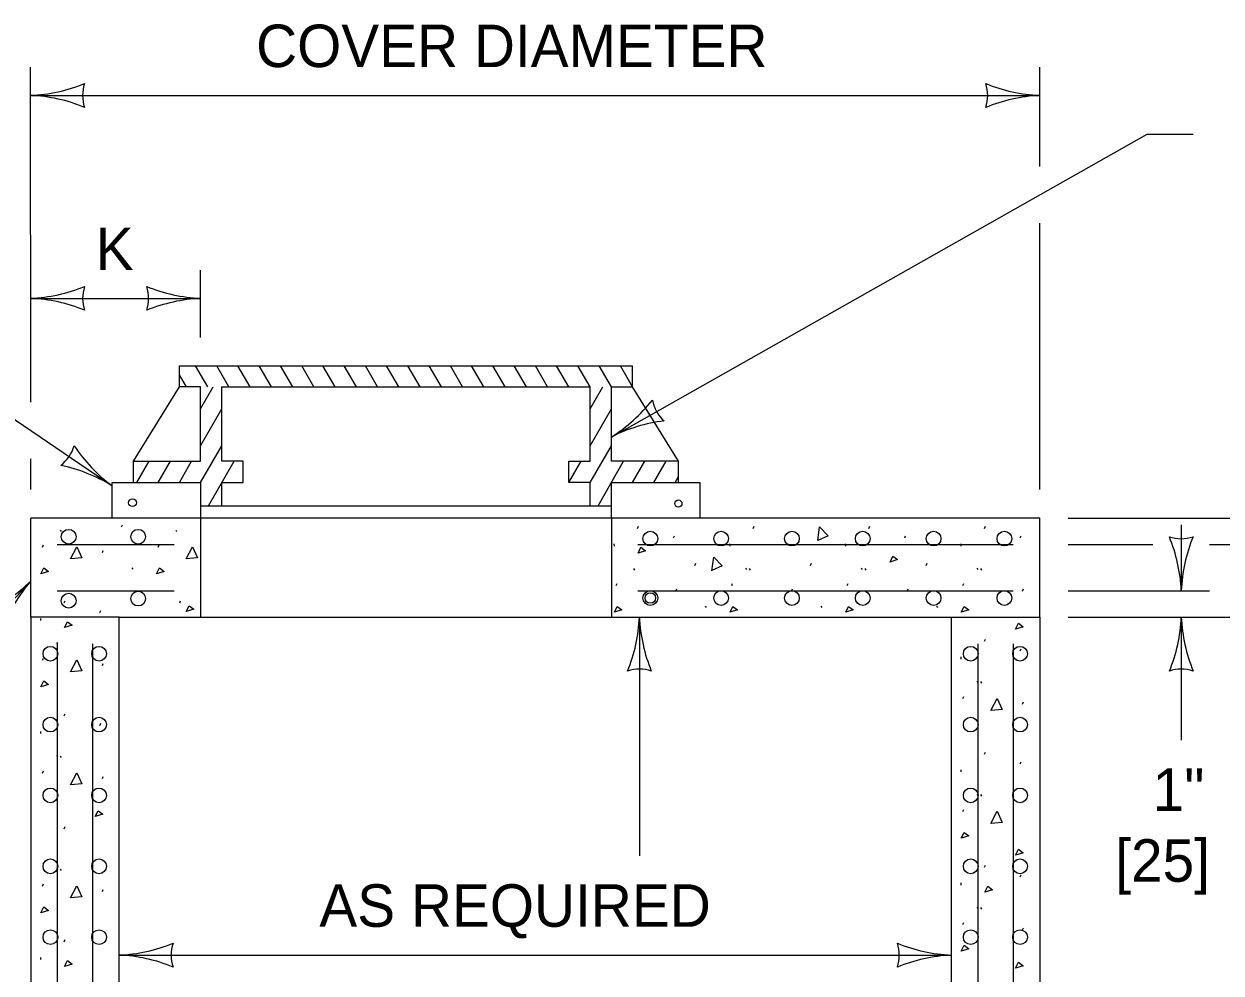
# Model space of a CAD drawing. Extents: x 49991.4 to 50028.3, y 49987.6 to 50011.4.
# Drawn here: x 50007.028 to 50008.719, y 49990.975 to 49992.315 of the extents above; entities that cross this region are included whole.
import ezdxf

# ---------------------------------------------------------------- set-up
doc = ezdxf.new("R2010")
doc.units = 0
for name, color, linetype in [('Level 1', 7, 'Continuous'), ('Level 2', 7, 'Continuous'), ('Level 3', 7, 'Continuous')]:
    doc.layers.add(name, color=color, linetype=linetype)

msp = doc.modelspace()

# ---------------------------------------------------------------- linework, layer by layer
at = {"layer": 'Level 1'}
for p, q in [((50007.2476, 49991.8027), (50007.2476, 49991.8327)), ((50007.2476, 49991.8327), (50007.2776, 49991.8327)), ((50007.2576, 49991.8027), (50007.2476, 49991.82)), ((50007.2876, 49991.8027), (50007.2703, 49991.8327)), ((50007.2776, 49991.8327), (50007.8876, 49991.8327)), ((50007.3176, 49991.8027), (50007.3003, 49991.8327)), ((50007.3476, 49991.8027), (50007.3303, 49991.8327)), ((50007.3776, 49991.8027), (50007.3603, 49991.8327)), ((50007.4076, 49991.8027), (50007.3903, 49991.8327)), ((50007.4376, 49991.8027), (50007.4203, 49991.8327)), ((50007.4676, 49991.8027), (50007.4503, 49991.8327)), ((50007.4976, 49991.8027), (50007.4803, 49991.8327)), ((50007.5276, 49991.8027), (50007.5103, 49991.8327)), ((50007.5576, 49991.8027), (50007.5403, 49991.8327)), ((50007.5876, 49991.8027), (50007.5703, 49991.8327)), ((50007.6176, 49991.8027), (50007.6003, 49991.8327)), ((50007.6476, 49991.8027), (50007.6303, 49991.8327)), ((50007.6776, 49991.8027), (50007.6603, 49991.8327)), ((50007.7076, 49991.8027), (50007.6903, 49991.8327)), ((50007.7376, 49991.8027), (50007.7203, 49991.8327)), ((50007.7676, 49991.8027), (50007.7503, 49991.8327)), ((50007.7976, 49991.8027), (50007.7803, 49991.8327)), ((50007.8276, 49991.8027), (50007.8103, 49991.8327)), ((50007.8576, 49991.8027), (50007.8403, 49991.8327)), ((50007.8876, 49991.8027), (50007.8703, 49991.8327)), ((50007.8876, 49991.8027), (50007.8876, 49991.8327)), ((50007.1826, 49991.6977), (50007.2476, 49991.8027)), ((50007.2776, 49991.8027), (50007.2476, 49991.8027)), ((50007.2776, 49991.6977), (50007.2776, 49991.8027)), ((50007.2776, 49991.7716), (50007.2955, 49991.8027)), ((50007.3076, 49991.6977), (50007.3076, 49991.8027)), ((50007.3076, 49991.8027), (50007.8276, 49991.8027)), ((50007.8276, 49991.6977), (50007.8276, 49991.8027)), ((50007.8276, 49991.7716), (50007.8455, 49991.8027)), ((50007.8576, 49991.6977), (50007.8576, 49991.8027)), ((50007.8576, 49991.8027), (50007.8876, 49991.8027)), ((50007.9526, 49991.6977), (50007.8876, 49991.8027)), ((50007.2776, 49991.7196), (50007.3076, 49991.7716)), ((50007.8276, 49991.7197), (50007.8576, 49991.7716)), ((50007.2776, 49991.6677), (50007.3076, 49991.7196)), ((50007.8276, 49991.6677), (50007.8576, 49991.7196)), ((50007.1826, 49991.6677), (50007.1826, 49991.6977)), ((50007.1826, 49991.6977), (50007.2776, 49991.6977)), ((50007.1876, 49991.6677), (50007.2049, 49991.6977)), ((50007.2176, 49991.6677), (50007.2349, 49991.6977)), ((50007.2476, 49991.6677), (50007.2649, 49991.6977)), ((50007.2888, 49991.6351), (50007.3249, 49991.6977)), ((50007.3376, 49991.6977), (50007.3076, 49991.6977)), ((50007.3376, 49991.6677), (50007.3376, 49991.6977)), ((50007.7976, 49991.6677), (50007.7976, 49991.6977)), ((50007.7976, 49991.6977), (50007.8276, 49991.6977)), ((50007.7976, 49991.6677), (50007.8149, 49991.6977)), ((50007.8388, 49991.6351), (50007.8749, 49991.6977)), ((50007.9526, 49991.6977), (50007.8576, 49991.6977)), ((50007.8876, 49991.6677), (50007.9049, 49991.6977)), ((50007.9176, 49991.6677), (50007.9349, 49991.6977)), ((50007.9526, 49991.6677), (50007.9526, 49991.6977)), ((50007.1526, 49991.6177), (50007.1526, 49991.6677)), ((50007.1526, 49991.6677), (50007.2776, 49991.6677)), ((50007.2776, 49991.6677), (50007.2776, 49991.6177)), ((50007.3076, 49991.6351), (50007.3076, 49991.6677)), ((50007.3076, 49991.6677), (50007.3376, 49991.6677)), ((50007.8276, 49991.6677), (50007.7976, 49991.6677)), ((50007.8276, 49991.6351), (50007.8276, 49991.6677)), ((50007.8576, 49991.6177), (50007.8576, 49991.6677)), ((50007.8576, 49991.6677), (50007.9826, 49991.6677)), ((50007.9476, 49991.6677), (50007.9526, 49991.6763)), ((50007.9826, 49991.6677), (50007.9826, 49991.6177)), ((50007.2776, 49991.6351), (50007.8576, 49991.6351)), ((50007.0376, 49991.4777), (50007.0376, 49991.6177)), ((50008.4626, 49991.6177), (50007.0376, 49991.6177)), ((50007.2776, 49991.6177), (50007.2776, 49991.4777)), ((50007.8576, 49991.6177), (50007.8576, 49991.4777)), ((50008.4626, 49991.4777), (50008.4626, 49991.6177)), ((50007.0791, 49991.6005), (50007.0805, 49991.5985)), ((50007.1657, 49991.6052), (50007.1671, 49991.6082)), ((50007.2424, 49991.6005), (50007.2437, 49991.5985)), ((50007.8947, 49991.6031), (50007.896, 49991.6061)), ((50008.0579, 49991.6031), (50008.0593, 49991.6061)), ((50008.2212, 49991.6031), (50008.2225, 49991.6061)), ((50008.3845, 49991.6031), (50008.3858, 49991.6061)), ((50007.0751, 49991.5801), (50007.2401, 49991.5801)), ((50007.8612, 49991.5811), (50007.8615, 49991.5781)), ((50007.8951, 49991.5801), (50008.4251, 49991.5801)), ((50007.9453, 49991.5895), (50007.9467, 49991.5925)), ((50008.0245, 49991.5811), (50008.0248, 49991.5781)), ((50008.1877, 49991.5811), (50008.1881, 49991.5781)), ((50008.2718, 49991.5895), (50008.2732, 49991.5925)), ((50008.351, 49991.5811), (50008.3513, 49991.5781)), ((50008.4351, 49991.5895), (50008.4364, 49991.5925)), ((50007.0544, 49991.5766), (50007.0557, 49991.5796)), ((50007.1388, 49991.5689), (50007.1401, 49991.5719)), ((50007.2177, 49991.5766), (50007.219, 49991.5796)), ((50007.1804, 49991.5476), (50007.1817, 49991.5456)), ((50007.889, 49991.5462), (50007.8903, 49991.5442)), ((50007.9756, 49991.5508), (50007.9769, 49991.5538)), ((50008.0472, 49991.5469), (50008.0485, 49991.5449)), ((50008.0523, 49991.5462), (50008.0536, 49991.5442)), ((50008.1389, 49991.5508), (50008.1402, 49991.5538)), ((50008.2105, 49991.5469), (50008.2118, 49991.5449)), ((50008.2155, 49991.5462), (50008.2169, 49991.5442)), ((50008.3021, 49991.5508), (50008.3035, 49991.5538)), ((50008.3737, 49991.5469), (50008.3751, 49991.5449)), ((50008.3788, 49991.5462), (50008.3801, 49991.5442)), ((50007.0751, 49991.5151), (50007.2401, 49991.5151)), ((50007.8643, 49991.5223), (50007.8656, 49991.5252)), ((50007.8951, 49991.5151), (50008.4251, 49991.5151)), ((50007.9486, 49991.5146), (50007.95, 49991.5176)), ((50008.0275, 49991.5223), (50008.0289, 49991.5252)), ((50008.1119, 49991.5146), (50008.1132, 49991.5176)), ((50008.1908, 49991.5223), (50008.1921, 49991.5252)), ((50008.2752, 49991.5146), (50008.2765, 49991.5176)), ((50008.3541, 49991.5223), (50008.3554, 49991.5252)), ((50008.4384, 49991.5146), (50008.4398, 49991.5176)), ((50007.0848, 49991.498), (50007.0861, 49991.501)), ((50007.2481, 49991.498), (50007.2494, 49991.501)), ((50007.1355, 49991.4843), (50007.1368, 49991.4873)), ((50007.9903, 49991.4933), (50007.9916, 49991.4913)), ((50008.1535, 49991.4933), (50008.1549, 49991.4913)), ((50008.3168, 49991.4933), (50008.3181, 49991.4913)), ((50007.1626, 49991.4777), (50007.0376, 49991.4777)), ((50007.0376, 49991.4777), (50007.0376, 49989.7777)), ((50007.0513, 49991.476), (50007.0517, 49991.473)), ((50008.3376, 49991.4777), (50008.4626, 49991.4777)), ((50008.4626, 49991.4777), (50008.4626, 49989.7777)), ((50008.3845, 49991.4437), (50008.3858, 49991.4467)), ((50007.0741, 49991.4418), (50007.0754, 49991.4398)), ((50007.0751, 49991.4401), (50007.0751, 49989.8151)), ((50007.1251, 49991.4401), (50007.1251, 49989.8151)), ((50008.3751, 49991.4401), (50008.3751, 49989.8151)), ((50008.4251, 49991.4401), (50008.4251, 49989.8151)), ((50008.4351, 49991.43), (50008.4364, 49991.433)), ((50007.0544, 49991.4171), (50007.0557, 49991.4201)), ((50007.1388, 49991.4095), (50007.1401, 49991.4125)), ((50008.351, 49991.4216), (50008.3513, 49991.4186)), ((50008.3737, 49991.3875), (50008.3751, 49991.3855)), ((50008.3788, 49991.3867), (50008.3801, 49991.3847)), ((50008.3541, 49991.3628), (50008.3554, 49991.3658)), ((50008.4384, 49991.3551), (50008.4398, 49991.3581)), ((50007.0848, 49991.3385), (50007.0861, 49991.3415)), ((50007.1355, 49991.3249), (50007.1368, 49991.3279)), ((50007.0513, 49991.3165), (50007.0517, 49991.3135)), ((50007.0741, 49991.2824), (50007.0754, 49991.2804)), ((50007.0791, 49991.2816), (50007.0805, 49991.2796)), ((50008.3845, 49991.2842), (50008.3858, 49991.2872)), ((50007.0544, 49991.2577), (50007.0557, 49991.2607)), ((50008.351, 49991.2622), (50008.3513, 49991.2592)), ((50008.4351, 49991.2705), (50008.4364, 49991.2735)), ((50007.1388, 49991.25), (50007.1401, 49991.253)), ((50008.3737, 49991.228), (50008.3751, 49991.226)), ((50008.3788, 49991.2273), (50008.3801, 49991.2253)), ((50008.3541, 49991.2033), (50008.3554, 49991.2063)), ((50007.0848, 49991.1791), (50007.0861, 49991.1821)), ((50008.3845, 49991.1247), (50008.3858, 49991.1277)), ((50007.0741, 49991.1229), (50007.0754, 49991.1209)), ((50007.0791, 49991.1221), (50007.0805, 49991.1201)), ((50008.4351, 49991.1111), (50008.4364, 49991.1141)), ((50007.0544, 49991.0982), (50007.0557, 49991.1012)), ((50007.1388, 49991.0906), (50007.1401, 49991.0935)), ((50008.351, 49991.1027), (50008.3513, 49991.0997)), ((50008.3737, 49991.0685), (50008.3751, 49991.0665)), ((50008.3788, 49991.0678), (50008.3801, 49991.0658)), ((50008.3541, 49991.0439), (50008.3554, 49991.0469)), ((50008.4384, 49991.0362), (50008.4398, 49991.0392)), ((50007.0848, 49991.0196), (50007.0861, 49991.0226)), ((50007.0513, 49990.9976), (50007.0517, 49990.9946))]:
    msp.add_line(p, q, dxfattribs=at)
for points in [[(50008.1491, 49991.586), (50008.1517, 49991.6051), (50008.1637, 49991.5927), (50008.1494, 49991.5861)], [(50007.0938, 49991.5599), (50007.1028, 49991.5769), (50007.1098, 49991.5613), (50007.0941, 49991.5599)], [(50007.2571, 49991.5599), (50007.2661, 49991.5769), (50007.2731, 49991.5613), (50007.2574, 49991.5599)], [(50007.8953, 49991.5681), (50007.8993, 49991.5765), (50007.906, 49991.5715), (50007.8953, 49991.5681)], [(50008.2511, 49991.5555), (50008.2551, 49991.5639), (50008.2618, 49991.5589), (50008.2511, 49991.5555)], [(50007.0521, 49991.5389), (50007.0561, 49991.5473), (50007.0627, 49991.5423), (50007.0521, 49991.5389)], [(50007.2153, 49991.5389), (50007.2193, 49991.5473), (50007.226, 49991.5423), (50007.2153, 49991.5389)], [(50007.9995, 49991.5433), (50008.0021, 49991.5623), (50008.014, 49991.55), (50007.9997, 49991.5434)], [(50007.2572, 49991.4856), (50007.2612, 49991.4939), (50007.2679, 49991.4889), (50007.2572, 49991.4856)], [(50007.8619, 49991.4846), (50007.8659, 49991.4929), (50007.8726, 49991.4879), (50007.8619, 49991.4846)], [(50008.0252, 49991.4846), (50008.0292, 49991.4929), (50008.0359, 49991.4879), (50008.0252, 49991.4846)], [(50008.1885, 49991.4846), (50008.1925, 49991.4929), (50008.1991, 49991.4879), (50008.1885, 49991.4846)], [(50008.3517, 49991.4846), (50008.3557, 49991.4929), (50008.3624, 49991.4879), (50008.3517, 49991.4846)], [(50007.0855, 49991.463), (50007.0895, 49991.4713), (50007.0961, 49991.4664), (50007.0855, 49991.463)], [(50008.4285, 49991.4608), (50008.4325, 49991.4691), (50008.4392, 49991.4641), (50008.4285, 49991.4608)], [(50007.0938, 49991.4005), (50007.1028, 49991.4175), (50007.1098, 49991.4018), (50007.0941, 49991.4005)], [(50007.0521, 49991.3795), (50007.0561, 49991.3878), (50007.0627, 49991.3828), (50007.0521, 49991.3795)], [(50008.3935, 49991.3461), (50008.4025, 49991.3631), (50008.4095, 49991.3475), (50008.3938, 49991.3461)], [(50007.0938, 49991.241), (50007.1028, 49991.258), (50007.1098, 49991.2423), (50007.0941, 49991.241)], [(50007.1289, 49991.1963), (50007.1329, 49991.2046), (50007.1395, 49991.1996), (50007.1289, 49991.1963)], [(50008.3935, 49991.1867), (50008.4025, 49991.2037), (50008.4095, 49991.188), (50008.3938, 49991.1867)], [(50008.3517, 49991.1657), (50008.3557, 49991.174), (50008.3624, 49991.169), (50008.3517, 49991.1657)], [(50008.4285, 49991.1419), (50008.4325, 49991.1502), (50008.4392, 49991.1452), (50008.4285, 49991.1419)], [(50007.0938, 49991.0816), (50007.1028, 49991.0985), (50007.1098, 49991.0829), (50007.0941, 49991.0816)], [(50008.3851, 49991.0898), (50008.3891, 49991.0981), (50008.3958, 49991.0931), (50008.3851, 49991.0898)], [(50007.0521, 49991.0606), (50007.0561, 49991.0689), (50007.0627, 49991.0639), (50007.0521, 49991.0606)], [(50008.3517, 49991.0063), (50008.3557, 49991.0146), (50008.3624, 49991.0096), (50008.3517, 49991.0063)], [(50007.0855, 49990.9847), (50007.0895, 49990.993), (50007.0961, 49990.988), (50007.0855, 49990.9847)], [(50008.4285, 49990.9825), (50008.4325, 49990.9908), (50008.4392, 49990.9858), (50008.4285, 49990.9825)]]:
    msp.add_lwpolyline(points, dxfattribs=at)
msp.add_lwpolyline([(50007.1626, 49991.4777), (50008.3376, 49991.4777), (50008.3376, 49989.4277), (50007.1626, 49989.4277)], close=True, dxfattribs=at)
for centre, radius in [((50007.1814, 49991.6393), 0.00544), ((50007.9523, 49991.6381), 0.00503), ((50007.0913, 49991.5912), 0.0104), ((50007.1894, 49991.5912), 0.0104), ((50007.9126, 49991.5887), 0.0104), ((50008.0126, 49991.5887), 0.0104), ((50008.1126, 49991.5887), 0.0104), ((50008.2126, 49991.5887), 0.0104), ((50008.3126, 49991.5887), 0.0104), ((50008.4126, 49991.5887), 0.0104), ((50007.1894, 49991.504), 0.0104), ((50007.9126, 49991.5047), 0.0104), ((50008.0126, 49991.5047), 0.0104), ((50008.1126, 49991.5047), 0.0104), ((50008.2126, 49991.5047), 0.0104), ((50008.3126, 49991.5047), 0.0104), ((50008.4126, 49991.5047), 0.0104), ((50007.0913, 49991.501), 0.0104), ((50007.9126, 49991.5048), 0.0074), ((50007.0655, 49991.4261), 0.0104), ((50007.1342, 49991.4261), 0.0104), ((50008.3651, 49991.4261), 0.0104), ((50008.4347, 49991.4261), 0.0104), ((50007.0655, 49991.3261), 0.0104), ((50007.1342, 49991.3261), 0.0104), ((50008.3651, 49991.3261), 0.0104), ((50008.4347, 49991.3261), 0.0104), ((50007.0655, 49991.2261), 0.0104), ((50007.1342, 49991.2261), 0.0104), ((50008.3651, 49991.2261), 0.0104), ((50008.4347, 49991.2261), 0.0104), ((50007.0655, 49991.1261), 0.0104), ((50007.1342, 49991.1261), 0.0104), ((50008.3651, 49991.1261), 0.0104), ((50008.4347, 49991.1261), 0.0104), ((50007.0655, 49991.0261), 0.0104), ((50007.1342, 49991.0261), 0.0104), ((50008.3651, 49991.0261), 0.0104), ((50008.4347, 49991.0261), 0.0104)]:
    msp.add_circle(centre, radius, dxfattribs=at)
at = {"layer": 'Level 3'}
for p, q in [((50007.0376, 49991.7811), (50007.0375, 49992.2541)), ((50008.4625, 49992.1137), (50008.4625, 49992.2541)), ((50007.0375, 49992.2141), (50008.4625, 49992.2141)), ((50007.8576, 49991.732), (50008.6143, 49992.1594)), ((50008.6143, 49992.1594), (50008.6794, 49992.1594)), ((50008.4626, 49991.6577), (50008.4626, 49992.0337)), ((50007.2776, 49991.8725), (50007.2776, 49991.9677)), ((50007.0376, 49991.9277), (50007.2776, 49991.9277)), ((50006.9931, 49991.7712), (50007.1526, 49991.6632)), ((50007.0376, 49991.6577), (50007.0376, 49991.7011)), ((50008.5026, 49991.6177), (50009.1824, 49991.6177)), ((50008.6624, 49991.6081), (50008.6624, 49991.5151)), ((50008.5026, 49991.5801), (50008.6224, 49991.5801)), ((50008.7024, 49991.5801), (50008.9394, 49991.5801)), ((50006.9172, 49991.3999), (50007.0376, 49991.5287)), ((50008.5026, 49991.5151), (50008.7024, 49991.5151)), ((50007.8972, 49991.4777), (50007.8972, 49991.1407)), ((50008.5026, 49991.4777), (50009.1824, 49991.4777)), ((50008.6624, 49991.4777), (50008.6624, 49991.3043)), ((50007.1626, 49991.0007), (50008.3376, 49991.0007))]:
    msp.add_line(p, q, dxfattribs=at)
for centre, radius, start, end in [((50007.026, 49992.4468), 0.233, 272.8273, 292.0772), ((50007.1657, 49992.2141), 0.0548, 162.1388, 197.8612), ((50008.4716, 49992.4363), 0.2223, 247.456, 267.6395), ((50008.3342, 49992.2141), 0.0548, 342.1388, 17.8612), ((50007.0283, 49991.992), 0.2223, 67.456, 87.6395), ((50008.4739, 49991.9814), 0.233, 92.8273, 112.0772), ((50007.0261, 49992.1604), 0.233, 272.8273, 292.0772), ((50007.1658, 49991.9277), 0.0548, 162.1388, 197.8612), ((50007.2867, 49992.1499), 0.2223, 247.456, 267.6395), ((50007.1494, 49991.9277), 0.0548, 342.1388, 17.8612), ((50007.0284, 49991.7056), 0.2223, 67.456, 87.6395), ((50007.2891, 49991.695), 0.233, 92.8273, 112.0772), ((50007.7331, 49991.929), 0.233, 302.2857, 321.5355), ((50007.9692, 49991.795), 0.0548, 191.5972, 227.3196), ((50007.9589, 49991.5341), 0.2223, 96.9144, 117.0979), ((50007.0464, 49991.7351), 0.0548, 308.0383, 343.7607), ((50007.2847, 49991.842), 0.2223, 213.3555, 233.539), ((50007.0316, 49991.4641), 0.233, 58.7268, 77.9767), ((50008.6624, 49991.6433), 0.0548, 252.1388, 287.8612), ((50008.4297, 49991.5036), 0.233, 2.8273, 22.0772), ((50008.8845, 49991.506), 0.2223, 157.456, 177.6395), ((50006.8816, 49991.6871), 0.2223, 294.3866, 314.5701), ((50007.2154, 49991.3782), 0.233, 139.7579, 159.0077), ((50007.6751, 49991.4869), 0.2223, 337.456, 357.6395), ((50008.1299, 49991.4892), 0.233, 182.8273, 202.0772), ((50008.4403, 49991.4869), 0.2223, 337.456, 357.6395), ((50008.8951, 49991.4892), 0.233, 182.8273, 202.0772), ((50007.8972, 49991.3495), 0.0548, 72.1388, 107.8612), ((50008.6624, 49991.3495), 0.0548, 72.1388, 107.8612), ((50007.1511, 49991.2334), 0.233, 272.8273, 292.0772), ((50007.2908, 49991.0007), 0.0548, 162.1388, 197.8612), ((50008.3467, 49991.2229), 0.2223, 247.456, 267.6395), ((50008.2094, 49991.0007), 0.0548, 342.1388, 17.8612), ((50007.1534, 49990.7786), 0.2223, 67.456, 87.6395), ((50008.3491, 49990.768), 0.233, 92.8273, 112.0772)]:
    msp.add_arc(centre, radius, start, end, dxfattribs=at)

# ---------------------------------------------------------------- texts
at = {"layer": 'Level 2'}
for s, p in [('COVER DIAMETER', (50007.3559, 49992.2541)), ('K', (50007.1295, 49991.9677)), ('1"', (50008.622, 49991.2043)), ('[25]', (50008.5691, 49991.1043)), ('AS REQUIRED', (50007.4452, 49991.0407))]:
    msp.add_text(s, height=0.06, dxfattribs=at).set_placement(p)

doc.saveas('drawing.dxf')
